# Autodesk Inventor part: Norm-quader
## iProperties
Created: 2005-01
Part Number: Norm-quader
Material: 1.0037 St 37-2 / S235JR
Document SubType Name: Modellieren
Designer: mbm
Manufacturer: Standard
Standards Organization: Custom
Density: 1 g/cm^3
Catalog Web Link: www.mittelmeyer.de
Author: mbm
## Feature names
1. Extrusion2
